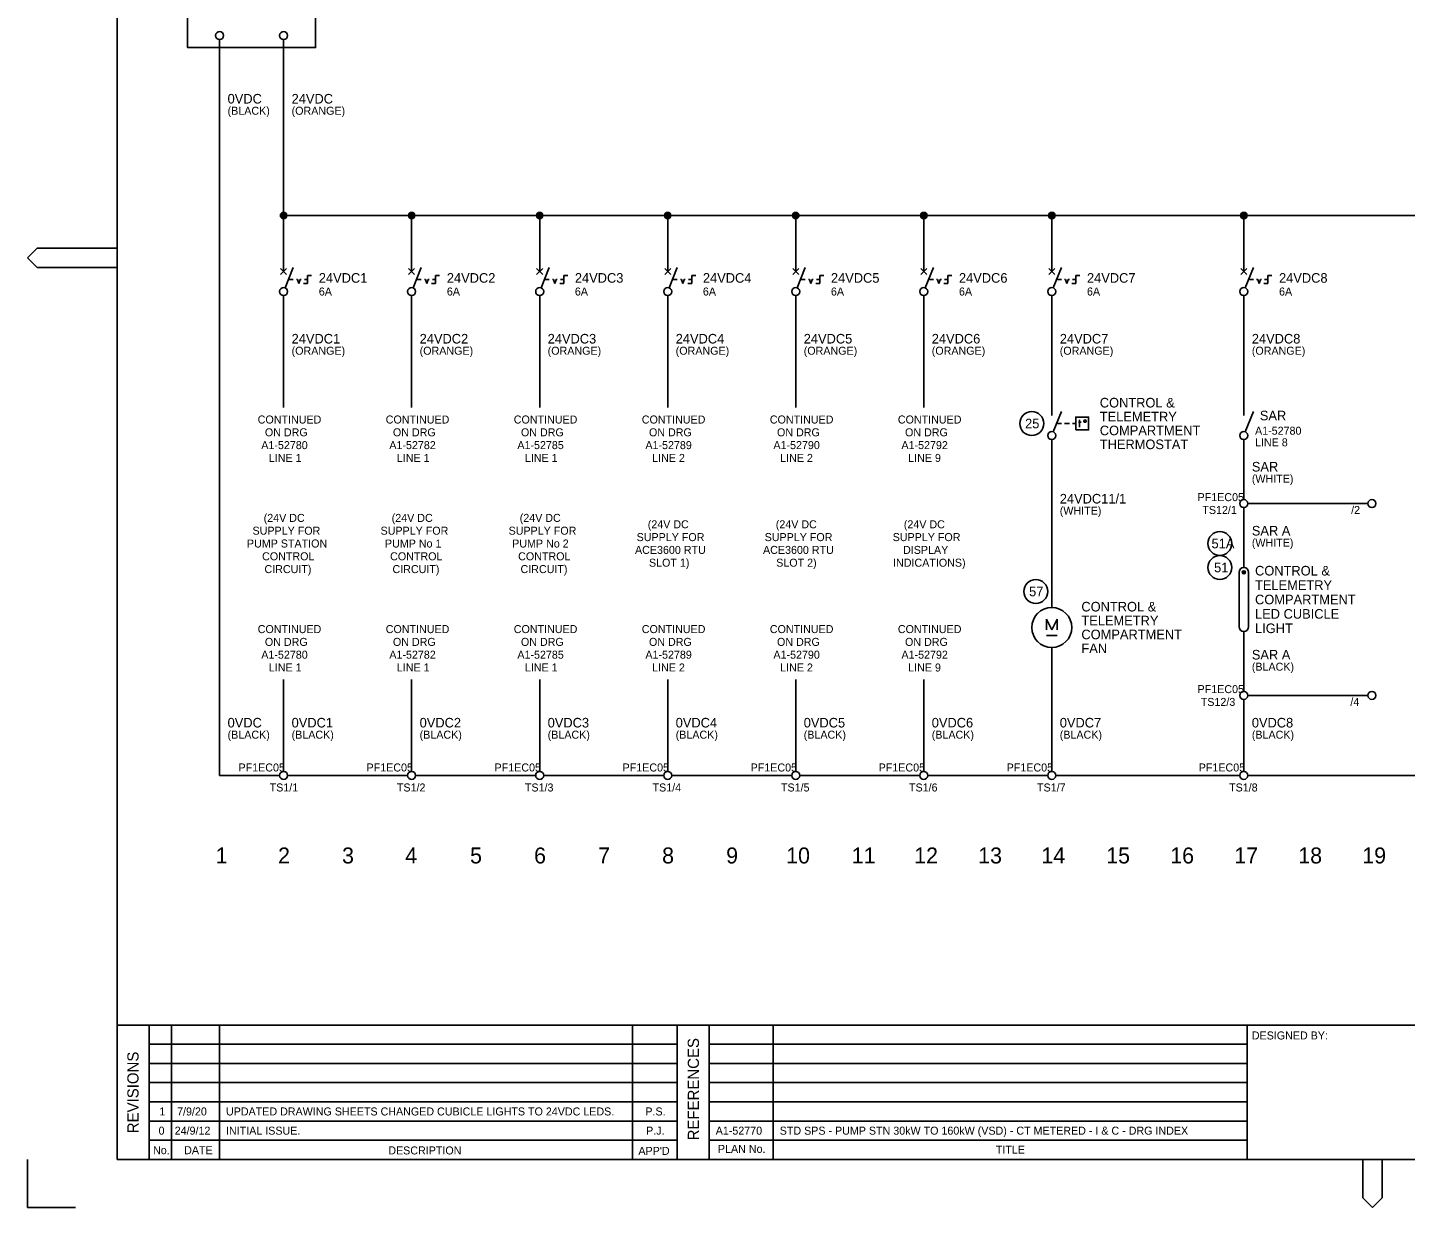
# Model space of a CAD drawing. Extents: x 0 to 841, y 0 to 594.
# Drawn here: x 0 to 430.5, y 0 to 368.8 of the extents above; entities that cross this region are included whole.
import ezdxf

# ---------------------------------------------------------------- set-up
doc = ezdxf.new("R2010")
doc.units = 0
for name, color, linetype in [('A1BORDER', 7, 'Continuous'), ('Level 1', 7, 'Continuous'), ('Level 10', 7, 'Continuous'), ('Level 4', 7, 'Continuous')]:
    doc.layers.add(name, color=color, linetype=linetype)

msp = doc.modelspace()

# ---------------------------------------------------------------- linework, layer by layer
at = {"layer": 'A1BORDER'}
for p, q in [((28, 581), (28, 15)), ((3, 299.76), (0, 296.76)), ((28, 299.76), (3, 299.76)), ((3, 293.76), (0, 296.76)), ((28, 293.76), (3, 293.76)), ((28, 57), (829, 57)), ((38, 15), (38, 57)), ((45, 15), (45, 57)), ((60, 15), (60, 57)), ((189, 15), (189, 57)), ((203, 15), (203, 57)), ((213, 15), (213, 57)), ((233, 15), (233, 57)), ((381, 15), (381, 57)), ((203, 51), (38, 51)), ((213, 51), (381, 51)), ((203, 45), (38, 45)), ((213, 45), (381, 45)), ((203, 39), (38, 39)), ((213, 39), (381, 39)), ((203, 33), (38, 33)), ((213, 33), (381, 33)), ((38, 27), (203, 27)), ((213, 27), (381, 27)), ((203, 21), (38, 21)), ((213, 21), (381, 21)), ((0, 0), (0, 15)), ((829, 15), (28, 15)), ((417.19, 15), (417.19, 3)), ((423.19, 15), (423.19, 3)), ((0, 0), (15, 0)), ((417.19, 3), (420.19, 0)), ((423.19, 3), (420.19, 0))]:
    msp.add_line(p, q, dxfattribs=at)
at = {"layer": 'Level 1'}
for p, q in [((60, 365), (60, 135)), ((80, 365), (80, 295)), ((80, 310), (540, 310)), ((120, 310), (120, 295)), ((160, 310), (160, 295)), ((200, 310), (200, 295)), ((240, 310), (240, 295)), ((280, 310), (280, 295)), ((320, 310), (320, 295)), ((380, 310), (380, 295)), ((79.06, 293.44), (80.94, 291.56)), ((80.94, 293.44), (79.06, 291.56)), ((80, 292.5), (80, 295)), ((80.46, 287.41), (83, 293.75)), ((119.06, 293.44), (120.94, 291.56)), ((120.94, 293.44), (119.06, 291.56)), ((120, 292.5), (120, 295)), ((120.46, 287.41), (123, 293.75)), ((159.06, 293.44), (160.94, 291.56)), ((160.94, 293.44), (159.06, 291.56)), ((160, 292.5), (160, 295)), ((160.46, 287.41), (163, 293.75)), ((199.06, 293.44), (200.94, 291.56)), ((200.94, 293.44), (199.06, 291.56)), ((200, 292.5), (200, 295)), ((200.46, 287.41), (203, 293.75)), ((239.06, 293.44), (240.94, 291.56)), ((240.94, 293.44), (239.06, 291.56)), ((240, 292.5), (240, 295)), ((240.46, 287.41), (243, 293.75)), ((279.06, 293.44), (280.94, 291.56)), ((280.94, 293.44), (279.06, 291.56)), ((280, 292.5), (280, 295)), ((280.46, 287.41), (283, 293.75)), ((319.06, 293.44), (320.94, 291.56)), ((320.94, 293.44), (319.06, 291.56)), ((320, 292.5), (320, 295)), ((320.46, 287.41), (323, 293.75)), ((379.06, 293.44), (380.94, 291.56)), ((380.94, 293.44), (379.06, 291.56)), ((380, 292.5), (380, 295)), ((380.46, 287.41), (383, 293.75)), ((80, 285), (80, 250)), ((120, 285), (120, 250)), ((160, 285), (160, 250)), ((200, 285), (200, 250)), ((240, 285), (240, 250)), ((280, 285), (280, 250)), ((320, 285), (320, 250)), ((380, 285), (380, 250)), ((320, 247.5), (320, 250)), ((380, 247.5), (380, 250)), ((380, 250), (380, 250)), ((320.46, 242.41), (323, 248.75)), ((321.5, 245), (323, 245)), ((324, 245), (325.5, 245)), ((326.5, 245), (327.5, 245)), ((320, 240), (320, 187.5)), ((380, 240), (380, 240)), ((380, 221.25), (380, 240)), ((381.25, 220), (418.75, 220)), ((380, 200), (380, 218.75)), ((380, 161.25), (380, 180)), ((320, 136.25), (320, 175)), ((80, 136.25), (80, 165)), ((120, 136.25), (120, 165)), ((160, 136.25), (160, 165)), ((200, 136.25), (200, 165)), ((240, 136.25), (240, 165)), ((280, 136.25), (280, 165)), ((381.25, 160), (418.75, 160)), ((380, 136.25), (380, 158.75)), ((60, 135), (78.75, 135)), ((81.25, 135), (118.75, 135)), ((121.25, 135), (158.75, 135)), ((161.25, 135), (198.75, 135)), ((201.25, 135), (238.75, 135)), ((241.25, 135), (278.75, 135)), ((281.25, 135), (318.75, 135)), ((321.25, 135), (378.75, 135)), ((381.25, 135), (458.75, 135))]:
    msp.add_line(p, q, dxfattribs=at)
for points in [[(50, 432.5), (90, 432.5), (90, 362.5), (50, 362.5)], [(327.5, 243), (331.5, 243), (331.5, 247), (327.5, 247)]]:
    msp.add_lwpolyline(points, close=True, dxfattribs=at)
for points in [[(328.63, 246.13), (328.63, 243.87)], [(330.36, 245.38), (330.18, 245.42), (330.05, 245.56), (329.99, 245.76), (330.05, 245.94), (330.18, 246.07), (330.36, 246.13), (330.56, 246.07), (330.7, 245.94), (330.74, 245.76), (330.7, 245.56), (330.56, 245.42), (330.36, 245.38)], [(328.38, 245.38), (329.13, 245.38)]]:
    msp.add_lwpolyline(points, dxfattribs=at)
for centre, radius in [((80, 286.25), 1.25), ((120, 286.25), 1.25), ((160, 286.25), 1.25), ((200, 286.25), 1.25), ((240, 286.25), 1.25), ((280, 286.25), 1.25), ((320, 286.25), 1.25), ((380, 286.25), 1.25), ((313.75, 245), 3.75), ((320, 241.25), 1.25), ((380, 220), 1.25), ((420, 220), 1.25), ((372.5, 207.5), 3.75), ((372.5, 200), 3.75), ((315, 192.5), 3.75), ((380, 160), 1.25), ((420, 160), 1.25)]:
    msp.add_circle(centre, radius, dxfattribs=at)
at = {"layer": 'Level 10'}
for p, q in [((79, 310), (80.99, 310)), ((79.05, 310.3), (80.95, 310.3)), ((79.2, 310.6), (80.8, 310.6)), ((79.56, 310.9), (80.44, 310.9)), ((80, 311), (80, 311)), ((119, 310), (120.99, 310)), ((119.05, 310.3), (120.95, 310.3)), ((119.2, 310.6), (120.8, 310.6)), ((119.56, 310.9), (120.44, 310.9)), ((120, 311), (120, 311)), ((159, 310), (160.99, 310)), ((159.05, 310.3), (160.95, 310.3)), ((159.2, 310.6), (160.8, 310.6)), ((159.56, 310.9), (160.44, 310.9)), ((160, 311), (160, 311)), ((199, 310), (200.99, 310)), ((199.05, 310.3), (200.95, 310.3)), ((199.2, 310.6), (200.8, 310.6)), ((199.56, 310.9), (200.44, 310.9)), ((200, 311), (200, 311)), ((239, 310), (240.99, 310)), ((239.05, 310.3), (240.95, 310.3)), ((239.2, 310.6), (240.8, 310.6)), ((239.56, 310.9), (240.44, 310.9)), ((240, 311), (240, 311)), ((279, 310), (280.99, 310)), ((279.05, 310.3), (280.95, 310.3)), ((279.2, 310.6), (280.8, 310.6)), ((279.56, 310.9), (280.44, 310.9)), ((280, 311), (280, 311)), ((319, 310), (320.99, 310)), ((319.05, 310.3), (320.95, 310.3)), ((319.2, 310.6), (320.8, 310.6)), ((319.56, 310.9), (320.44, 310.9)), ((320, 311), (320, 311)), ((379, 310), (380.99, 310)), ((379.05, 310.3), (380.95, 310.3)), ((379.2, 310.6), (380.8, 310.6)), ((379.56, 310.9), (380.44, 310.9)), ((380, 311), (380, 311)), ((79.05, 309.7), (80.95, 309.7)), ((79.2, 309.4), (80.8, 309.4)), ((79.56, 309.1), (80.44, 309.1)), ((119.05, 309.7), (120.95, 309.7)), ((119.2, 309.4), (120.8, 309.4)), ((119.56, 309.1), (120.44, 309.1)), ((159.05, 309.7), (160.95, 309.7)), ((159.2, 309.4), (160.8, 309.4)), ((159.56, 309.1), (160.44, 309.1)), ((199.05, 309.7), (200.95, 309.7)), ((199.2, 309.4), (200.8, 309.4)), ((199.56, 309.1), (200.44, 309.1)), ((239.05, 309.7), (240.95, 309.7)), ((239.2, 309.4), (240.8, 309.4)), ((239.56, 309.1), (240.44, 309.1)), ((279.05, 309.7), (280.95, 309.7)), ((279.2, 309.4), (280.8, 309.4)), ((279.56, 309.1), (280.44, 309.1)), ((319.05, 309.7), (320.95, 309.7)), ((319.2, 309.4), (320.8, 309.4)), ((319.56, 309.1), (320.44, 309.1)), ((379.05, 309.7), (380.95, 309.7)), ((379.2, 309.4), (380.8, 309.4)), ((379.56, 309.1), (380.44, 309.1)), ((81.5, 290), (83, 290)), ((84, 290), (84.33, 290)), ((84.75, 288.75), (84.33, 290)), ((84.75, 288.75), (85.17, 290)), ((85.5, 290), (85.17, 290)), ((86.25, 288.75), (87.5, 288.75)), ((86.5, 290), (87.5, 290)), ((87.5, 288.75), (87.5, 291.25)), ((87.5, 291.25), (88.75, 291.25)), ((121.5, 290), (123, 290)), ((124, 290), (124.33, 290)), ((124.75, 288.75), (124.33, 290)), ((124.75, 288.75), (125.17, 290)), ((125.5, 290), (125.17, 290)), ((126.25, 288.75), (127.5, 288.75)), ((126.5, 290), (127.5, 290)), ((127.5, 288.75), (127.5, 291.25)), ((127.5, 291.25), (128.75, 291.25)), ((161.5, 290), (163, 290)), ((164, 290), (164.33, 290)), ((164.75, 288.75), (164.33, 290)), ((164.75, 288.75), (165.17, 290)), ((165.5, 290), (165.17, 290)), ((166.25, 288.75), (167.5, 288.75)), ((166.5, 290), (167.5, 290)), ((167.5, 288.75), (167.5, 291.25)), ((167.5, 291.25), (168.75, 291.25)), ((201.5, 290), (203, 290)), ((204, 290), (204.33, 290)), ((204.75, 288.75), (204.33, 290)), ((204.75, 288.75), (205.17, 290)), ((205.5, 290), (205.17, 290)), ((206.25, 288.75), (207.5, 288.75)), ((206.5, 290), (207.5, 290)), ((207.5, 288.75), (207.5, 291.25)), ((207.5, 291.25), (208.75, 291.25)), ((241.5, 290), (243, 290)), ((244, 290), (244.33, 290)), ((244.75, 288.75), (244.33, 290)), ((244.75, 288.75), (245.17, 290)), ((245.5, 290), (245.17, 290)), ((246.25, 288.75), (247.5, 288.75)), ((246.5, 290), (247.5, 290)), ((247.5, 288.75), (247.5, 291.25)), ((247.5, 291.25), (248.75, 291.25)), ((281.5, 290), (283, 290)), ((284, 290), (284.33, 290)), ((284.75, 288.75), (284.33, 290)), ((284.75, 288.75), (285.17, 290)), ((285.5, 290), (285.17, 290)), ((286.25, 288.75), (287.5, 288.75)), ((286.5, 290), (287.5, 290)), ((287.5, 288.75), (287.5, 291.25)), ((287.5, 291.25), (288.75, 291.25)), ((321.5, 290), (323, 290)), ((324, 290), (324.33, 290)), ((324.75, 288.75), (324.33, 290)), ((324.75, 288.75), (325.17, 290)), ((325.5, 290), (325.17, 290)), ((326.25, 288.75), (327.5, 288.75)), ((326.5, 290), (327.5, 290)), ((327.5, 288.75), (327.5, 291.25)), ((327.5, 291.25), (328.75, 291.25)), ((381.5, 290), (383, 290)), ((384, 290), (384.33, 290)), ((384.75, 288.75), (384.33, 290)), ((384.75, 288.75), (385.17, 290)), ((385.5, 290), (385.17, 290)), ((386.25, 288.75), (387.5, 288.75)), ((386.5, 290), (387.5, 290)), ((387.5, 288.75), (387.5, 291.25)), ((387.5, 291.25), (388.75, 291.25)), ((380.46, 242.41), (383, 248.75)), ((378.5, 181.5), (378.5, 198.5)), ((379.5, 198.5), (379.5, 198.5)), ((379.8, 198.04), (379.8, 198.96)), ((380.1, 198.01), (380.1, 198.99)), ((380.4, 198.2), (380.4, 198.8)), ((381.5, 198.5), (381.5, 181.5)), ((318.33, 180.5), (318.33, 183.83)), ((318.33, 183.83), (320, 180.5)), ((320, 180.5), (321.67, 183.83)), ((321.67, 183.83), (321.67, 180.5)), ((318.34, 178.75), (321.68, 178.75))]:
    msp.add_line(p, q, dxfattribs=at)
for centre, radius in [((80, 310), 1), ((120, 310), 1), ((160, 310), 1), ((200, 310), 1), ((240, 310), 1), ((280, 310), 1), ((320, 310), 1), ((380, 310), 1), ((380, 241.25), 1.25), ((380, 198.5), 0.5), ((320, 181.25), 6.25), ((80, 135), 1.25), ((120, 135), 1.25), ((160, 135), 1.25), ((200, 135), 1.25), ((240, 135), 1.25), ((280, 135), 1.25), ((320, 135), 1.25), ((380, 135), 1.25)]:
    msp.add_circle(centre, radius, dxfattribs=at)
for centre, start, end in [((380, 198.5), 0, 180), ((380, 181.5), 180, 0)]:
    msp.add_arc(centre, 1.5, start, end, dxfattribs=at)
at = {"layer": 'Level 4'}
for centre in [(60, 366.25), (80, 366.25)]:
    msp.add_circle(centre, 1.25, dxfattribs=at)

# ---------------------------------------------------------------- texts
at = {"layer": 'A1BORDER'}
for s, p in [('REFERENCES', (209.76, 20.96)), ('REVISIONS', (34.68, 23.2))]:
    msp.add_text(s, height=3.5, rotation=90, dxfattribs=at).set_placement(p)
for s, p in [('DESIGNED BY:', (382.5, 52.5)), ('No.', (39.21, 16.65)), ('DATE', (48.92, 16.65)), ('DESCRIPTION', (112.71, 16.57)), ("APP'D", (190.85, 16.44)), ('PLAN No.', (215.69, 17.06)), ('TITLE', (302.5, 16.81))]:
    msp.add_text(s, height=2.5, dxfattribs=at).set_placement(p)
at = {"layer": 'Level 1'}
for s, height, p in [('0VDC', 3, (62.5, 345)), ('24VDC', 3, (82.5, 345)), ('(BLACK)', 2.5, (62.5, 341.5)), ('(ORANGE)', 2.5, (82.5, 341.5)), ('24VDC1', 3, (91, 289)), ('24VDC2', 3, (131, 289)), ('24VDC3', 3, (171, 289)), ('24VDC4', 3, (211, 289)), ('24VDC5', 3, (251, 289)), ('24VDC6', 3, (291, 289)), ('24VDC7', 3, (331, 289)), ('24VDC8', 3, (391, 289)), ('6A', 2.5, (91, 285)), ('6A', 2.5, (131, 285)), ('6A', 2.5, (171, 285)), ('6A', 2.5, (211, 285)), ('6A', 2.5, (251, 285)), ('6A', 2.5, (291, 285)), ('6A', 2.5, (331, 285)), ('6A', 2.5, (391, 285)), ('24VDC1', 3, (82.5, 270)), ('24VDC2', 3, (122.5, 270)), ('24VDC3', 3, (162.5, 270)), ('24VDC4', 3, (202.5, 270)), ('24VDC5', 3, (242.5, 270)), ('24VDC6', 3, (282.5, 270)), ('24VDC7', 3, (322.5, 270)), ('24VDC8', 3, (382.5, 270)), ('(ORANGE)', 2.5, (82.5, 266.5)), ('(ORANGE)', 2.5, (122.5, 266.5)), ('(ORANGE)', 2.5, (162.5, 266.5)), ('(ORANGE)', 2.5, (202.5, 266.5)), ('(ORANGE)', 2.5, (242.5, 266.5)), ('(ORANGE)', 2.5, (282.5, 266.5)), ('(ORANGE)', 2.5, (322.5, 266.5)), ('(ORANGE)', 2.5, (382.5, 266.5)), ('CONTROL &', 3, (335, 250.01)), ('CONTINUED', 2.5, (71.91, 245)), ('CONTINUED', 2.5, (111.91, 245)), ('CONTINUED', 2.5, (151.91, 245)), ('CONTINUED', 2.5, (191.91, 245)), ('CONTINUED', 2.5, (231.91, 245)), ('CONTINUED', 2.5, (271.91, 245)), ('25', 3, (311.66, 243.5)), ('TELEMETRY', 3, (335, 245.67)), ('SAR', 3, (385, 246)), ('ON DRG', 2.5, (74.15, 241)), ('ON DRG', 2.5, (114.15, 241)), ('ON DRG', 2.5, (154.15, 241)), ('ON DRG', 2.5, (194.15, 241)), ('ON DRG', 2.5, (234.15, 241)), ('ON DRG', 2.5, (274.15, 241)), ('COMPARTMENT', 3, (335, 241.33)), ('A1-52780', 2.5, (383.5, 241.5)), ('A1-52780', 2.5, (73.03, 237)), ('A1-52782', 2.5, (113.03, 237)), ('A1-52785', 2.5, (153.03, 237)), ('A1-52789', 2.5, (193.03, 237)), ('A1-52790', 2.5, (233.03, 237)), ('A1-52792', 2.5, (273.03, 237)), ('THERMOSTAT', 3, (335, 236.99)), ('LINE 8', 2.5, (383.5, 237.88)), ('LINE 1', 2.5, (75.39, 233)), ('LINE 1', 2.5, (115.39, 233)), ('LINE 1', 2.5, (155.39, 233)), ('LINE 2', 2.5, (195.14, 233)), ('LINE 2', 2.5, (235.14, 233)), ('LINE 9', 2.5, (275.14, 233)), ('SAR', 3, (382.5, 230)), ('(WHITE)', 2.5, (382.5, 226.5)), ('24VDC11/1', 3, (322.5, 220)), ('PF1EC05', 2.5, (365.55, 220.74)), ('(24V DC', 2.5, (73.77, 214.25)), ('(24V DC', 2.5, (113.77, 214.25)), ('(24V DC', 2.5, (153.77, 214.25)), ('(WHITE)', 2.5, (322.5, 216.5)), ('TS12/1', 2.5, (367.04, 216.74)), ('/2', 2.5, (413.52, 216.74)), ('SUPPLY FOR', 2.5, (70.29, 210.25)), ('SUPPLY FOR', 2.5, (110.29, 210.25)), ('SUPPLY FOR', 2.5, (150.29, 210.25)), ('(24V DC', 2.5, (193.77, 212.25)), ('(24V DC', 2.5, (233.77, 212.25)), ('(24V DC', 2.5, (273.77, 212.25)), ('SAR A', 3, (382.5, 210)), ('PUMP STATION', 2.5, (68.54, 206.25)), ('PUMP No 1', 2.5, (111.66, 206.25)), ('PUMP No 2', 2.5, (151.41, 206.25)), ('ACE3600 RTU', 2.5, (189.79, 204.25)), ('SUPPLY FOR', 2.5, (190.29, 208.25)), ('ACE3600 RTU', 2.5, (229.79, 204.25)), ('SUPPLY FOR', 2.5, (230.29, 208.25)), ('SUPPLY FOR', 2.5, (270.29, 208.25)), ('DISPLAY', 2.5, (273.53, 204.25)), ('51A', 3, (369.91, 206)), ('(WHITE)', 2.5, (382.5, 206.5)), ('CONTROL', 2.5, (73.28, 202.25)), ('CONTROL', 2.5, (113.28, 202.25)), ('CONTROL', 2.5, (153.28, 202.25)), ('SLOT 1)', 2.5, (194.15, 200.25)), ('SLOT 2)', 2.5, (233.9, 200.25)), ('INDICATIONS)', 2.5, (270.41, 200.25)), ('CIRCUIT)', 2.5, (74.02, 198.25)), ('CIRCUIT)', 2.5, (114.02, 198.25)), ('CIRCUIT)', 2.5, (154.02, 198.25)), ('51', 3, (370.71, 198.5)), ('CONTROL &', 3, (383.5, 197.5)), ('57', 3, (312.91, 191)), ('TELEMETRY', 3, (383.5, 193)), ('COMPARTMENT', 3, (383.5, 188.5)), ('CONTROL &', 3, (329.25, 186.26)), ('LED CUBICLE', 3, (383.5, 184)), ('CONTINUED', 2.5, (71.91, 179.5)), ('CONTINUED', 2.5, (111.91, 179.5)), ('CONTINUED', 2.5, (151.91, 179.5)), ('CONTINUED', 2.5, (191.91, 179.5)), ('CONTINUED', 2.5, (231.91, 179.5)), ('CONTINUED', 2.5, (271.91, 179.5)), ('TELEMETRY', 3, (329.25, 181.92)), ('LIGHT', 3, (383.5, 179.5)), ('ON DRG', 2.5, (74.15, 175.5)), ('ON DRG', 2.5, (114.15, 175.5)), ('ON DRG', 2.5, (154.15, 175.5)), ('ON DRG', 2.5, (194.15, 175.5)), ('ON DRG', 2.5, (234.15, 175.5)), ('ON DRG', 2.5, (274.15, 175.5)), ('COMPARTMENT', 3, (329.25, 177.58)), ('A1-52780', 2.5, (73.03, 171.5)), ('A1-52782', 2.5, (113.03, 171.5)), ('A1-52785', 2.5, (153.03, 171.5)), ('A1-52789', 2.5, (193.03, 171.5)), ('A1-52790', 2.5, (233.03, 171.5)), ('A1-52792', 2.5, (273.03, 171.5)), ('FAN', 3, (329.25, 173.24)), ('SAR A', 3, (382.5, 171.25)), ('LINE 1', 2.5, (75.39, 167.5)), ('LINE 1', 2.5, (115.39, 167.5)), ('LINE 1', 2.5, (155.39, 167.5)), ('LINE 2', 2.5, (195.14, 167.5)), ('LINE 2', 2.5, (235.14, 167.5)), ('LINE 9', 2.5, (275.14, 167.5)), ('(BLACK)', 2.5, (382.5, 167.75)), ('PF1EC05', 2.5, (365.55, 160.74)), ('TS12/3', 2.5, (366.55, 156.74)), ('/4', 2.5, (413.27, 156.74)), ('0VDC', 3, (62.5, 150)), ('0VDC1', 3, (82.5, 150)), ('0VDC2', 3, (122.5, 150)), ('0VDC3', 3, (162.5, 150)), ('0VDC4', 3, (202.5, 150)), ('0VDC5', 3, (242.5, 150)), ('0VDC6', 3, (282.5, 150)), ('0VDC7', 3, (322.5, 150)), ('0VDC8', 3, (382.5, 150)), ('(BLACK)', 2.5, (62.5, 146.5)), ('(BLACK)', 2.5, (82.5, 146.5)), ('(BLACK)', 2.5, (122.5, 146.5)), ('(BLACK)', 2.5, (162.5, 146.5)), ('(BLACK)', 2.5, (202.5, 146.5)), ('(BLACK)', 2.5, (242.5, 146.5)), ('(BLACK)', 2.5, (282.5, 146.5)), ('(BLACK)', 2.5, (322.5, 146.5)), ('(BLACK)', 2.5, (382.5, 146.5)), ('PF1EC05', 2.5, (65.91, 136.25)), ('PF1EC05', 2.5, (105.91, 136.25)), ('PF1EC05', 2.5, (145.91, 136.25)), ('PF1EC05', 2.5, (185.91, 136.25)), ('PF1EC05', 2.5, (225.91, 136.25)), ('PF1EC05', 2.5, (265.91, 136.25)), ('PF1EC05', 2.5, (305.91, 136.25)), ('PF1EC05', 2.5, (365.91, 136.25)), ('TS1/1', 2.5, (75.64, 130)), ('TS1/2', 2.5, (115.39, 130)), ('TS1/3', 2.5, (155.39, 130)), ('TS1/4', 2.5, (195.27, 130)), ('TS1/5', 2.5, (235.39, 130)), ('TS1/6', 2.5, (275.39, 130)), ('TS1/7', 2.5, (315.39, 130)), ('TS1/8', 2.5, (375.39, 130)), ('1', 5, (58.76, 107.5)), ('2', 5, (78.26, 107.5)), ('3', 5, (98.26, 107.5)), ('4', 5, (118.01, 107.5)), ('5', 5, (138.26, 107.5)), ('6', 5, (158.26, 107.5)), ('7', 5, (178.26, 107.5)), ('8', 5, (198.26, 107.5)), ('9', 5, (218.26, 107.5)), ('10', 5, (237.01, 107.5)), ('11', 5, (257.51, 107.5)), ('12', 5, (277.01, 107.5)), ('13', 5, (297.01, 107.5)), ('14', 5, (316.76, 107.5)), ('15', 5, (337.01, 107.5)), ('16', 5, (357.01, 107.5)), ('17', 5, (377.01, 107.5)), ('18', 5, (397.01, 107.5)), ('19', 5, (417.01, 107.5)), ('1', 2.5, (41.19, 28.75)), ('7/9/20', 2.5, (46.72, 28.75)), ('UPDATED DRAWING SHEETS CHANGED CUBICLE LIGHTS TO 24VDC LEDS.', 2.5, (62, 28.75)), ('P.S.', 2.5, (193.02, 28.75)), ('0', 2.5, (40.94, 22.75)), ('24/9/12', 2.5, (45.97, 22.75)), ('INITIAL ISSUE.', 2.5, (62, 22.75)), ('P.J.', 2.5, (193.26, 22.75)), ('A1-52770', 2.5, (215, 22.75)), ('STD SPS - PUMP STN 30kW TO 160kW (VSD) - CT METERED - I & C - DRG INDEX', 2.5, (235, 22.75))]:
    msp.add_text(s, height=height, dxfattribs=at).set_placement(p)

doc.saveas('drawing.dxf')
